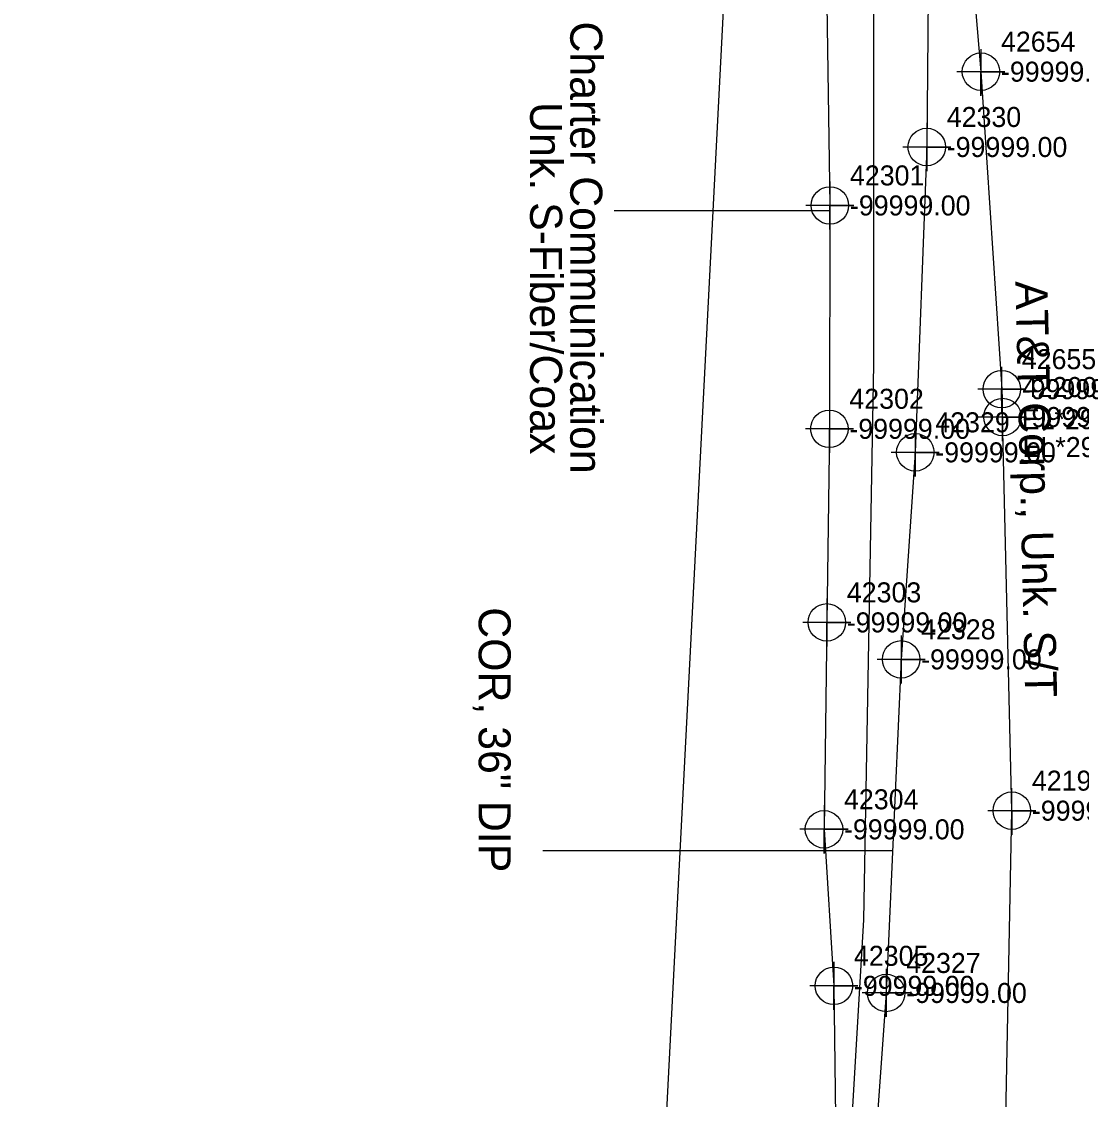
# Model space of a CAD drawing. Extents: x 2083698 to 2094313, y 743246 to 752873.
# Drawn here: x 2093623.5 to 2093755.8, y 746393.7 to 746528.4 of the extents above; entities that cross this region are included whole.
import ezdxf

# ---------------------------------------------------------------- set-up
doc = ezdxf.new("R2010")
doc.units = 0
for name, color, linetype in [('COGO Default Point Number', 7, 'Continuous'), ('Default Symbol CELL', 7, 'Continuous'), ('Default Symbol Cogo Number', 7, 'Continuous'), ('Exist Property Line', 7, 'Continuous'), ('Exist Property Line Leader', 7, 'Continuous'), ('Exist Right of Way Line', 7, 'Continuous'), ('Exist Right of Way Line Leader', 7, 'Continuous'), ('Exist Right of Way Line Text', 7, 'Continuous'), ('Exist Utilities Power UG Cable SUE LOS C', 7, 'Continuous'), ('Exist Utilities Telephone UG Conduit SUE LOS B', 7, 'Continuous'), ('Exist Utilities Telephone UG Conduit SUE LOS B Text', 7, 'Continuous'), ('Exist Utilities Telephone UG Conduit SUE LOS D', 7, 'Continuous'), ('Exist Utilities TV UG Cable SUE LOS B', 7, 'Continuous'), ('Exist Utilities TV UG Cable SUE LOS B Leader', 7, 'Continuous'), ('Exist Utilities TV UG Cable SUE LOS B Text', 7, 'Continuous'), ('Exist Utilities Water UG Line SUE LOS B', 7, 'Continuous'), ('Exist Utilities Water UG Line SUE LOS B Leader', 7, 'Continuous'), ('Exist Utilities Water UG Line SUE LOS B Text', 7, 'Continuous'), ('Scratch_Level_2', 7, 'Continuous'), ('Scratch_Level_3', 7, 'Continuous')]:
    doc.layers.add(name, color=color, linetype=linetype)

msp = doc.modelspace()

# ---------------------------------------------------------------- linework, layer by layer
at = {"layer": 'COGO Default Point Number'}
for points in [[(2093736.52, 746515.69), (2093736.52, 746509.69), (2093736.52, 746512.69), (2093739.52, 746512.69), (2093733.52, 746512.69)], [(2093735.09, 746477.55), (2093735.09, 746471.55), (2093735.09, 746474.55), (2093738.09, 746474.55), (2093732.09, 746474.55)], [(2093733.32, 746451.69), (2093733.32, 746445.69), (2093733.32, 746448.69), (2093736.32, 746448.69), (2093730.32, 746448.69)], [(2093731.46, 746410.02), (2093731.46, 746404.02), (2093731.46, 746407.02), (2093734.46, 746407.02), (2093728.46, 746407.02)]]:
    msp.add_lwpolyline(points, dxfattribs=at)
for centre in [(2093736.52, 746512.69), (2093735.09, 746474.55), (2093733.32, 746448.69), (2093731.46, 746407.02)]:
    msp.add_circle(centre, 2.34, dxfattribs=at)
at = {"layer": 'Exist Property Line Leader'}
for points in [[(2093724.43, 746508.39), (2093724.43, 746502.39), (2093724.43, 746505.39), (2093727.43, 746505.39), (2093721.43, 746505.39)], [(2093724.36, 746480.49), (2093724.36, 746474.49), (2093724.36, 746477.49), (2093727.36, 746477.49), (2093721.36, 746477.49)], [(2093724.04, 746456.31), (2093724.04, 746450.31), (2093724.04, 746453.31), (2093727.04, 746453.31), (2093721.04, 746453.31)], [(2093723.69, 746430.46), (2093723.69, 746424.46), (2093723.69, 746427.46), (2093726.69, 746427.46), (2093720.69, 746427.46)], [(2093724.93, 746410.91), (2093724.93, 746404.91), (2093724.93, 746407.91), (2093727.93, 746407.91), (2093721.93, 746407.91)]]:
    msp.add_lwpolyline(points, dxfattribs=at)
for centre in [(2093724.43, 746505.39), (2093724.36, 746477.49), (2093724.04, 746453.31), (2093723.69, 746427.46), (2093724.93, 746407.91)]:
    msp.add_circle(centre, 2.34, dxfattribs=at)
at = {"layer": 'Exist Right of Way Line Text'}
for points in [[(2093743.26, 746524.92), (2093743.29, 746519.1), (2093743.27, 746522.1), (2093746.29, 746522.1), (2093740.29, 746522.1)], [(2093745.85, 746485.25), (2093745.89, 746479.44), (2093745.87, 746482.44), (2093748.89, 746482.44), (2093742.89, 746482.44)], [(2093745.96, 746481.77), (2093745.99, 746475.96), (2093745.97, 746478.96), (2093748.99, 746478.96), (2093742.99, 746478.96)], [(2093747.11, 746432.6), (2093747.15, 746426.79), (2093747.13, 746429.79), (2093750.15, 746429.79), (2093744.15, 746429.79)]]:
    msp.add_lwpolyline(points, dxfattribs=at)
for centre in [(2093743.29, 746522.1), (2093745.89, 746482.44), (2093745.99, 746478.96), (2093747.15, 746429.79)]:
    msp.add_circle(centre, 2.34, dxfattribs=at)
at = {"layer": 'Exist Utilities Power UG Cable SUE LOS C'}
msp.add_line((2093711.24, 746532.37), (2093680.95, 745945.23), dxfattribs=at)
at = {"layer": 'Exist Utilities Telephone UG Conduit SUE LOS B'}
for points in [[(2093736.63, 746599.86), (2093737.4, 746591.68), (2093739.58, 746565.92), (2093743.29, 746522.1), (2093745.89, 746482.44)], [(2093744.82, 746339.36), (2093746.32, 746387.24), (2093747.15, 746429.79), (2093745.99, 746478.96)]]:
    msp.add_lwpolyline(points, dxfattribs=at)
at = {"layer": 'Exist Utilities Telephone UG Conduit SUE LOS D'}
msp.add_lwpolyline([(2093729.86, 746559.98), (2093729.86, 746485.51), (2093728.61, 746416.16), (2093711.62, 746127.01), (2093702.37, 745955.82), (2093693.11, 745784.64), (2093668.68, 745395.41), (2093654.74, 745161.51), (2093649.12, 745054.6), (2093640.35, 744903.62), (2093631.77, 744751.08), (2093623.85, 744627.43), (2093615.93, 744503.79), (2093603.66, 744373.9), (2093590.72, 744165.44), (2093582.98, 744085.27), (2093575.24, 744005.11), (2093571.65, 743852.76), (2093573.5, 743810.29), (2093555.01, 743734.28)], dxfattribs=at)
at = {"layer": 'Exist Utilities TV UG Cable SUE LOS B'}
msp.add_lwpolyline([(2093633.07, 746593.51), (2093662.38, 746588.07), (2093680.36, 746583.68), (2093688.75, 746580.8), (2093702.36, 746567.68), (2093717.61, 746549.77), (2093724.02, 746533.32), (2093724.43, 746505.39), (2093724.36, 746477.49), (2093724.04, 746453.31), (2093723.69, 746427.46), (2093724.93, 746407.91), (2093725.3, 746378.4), (2093722.23, 746347.81), (2093721.14, 746321.95), (2093719.64, 746295.64), (2093717.76, 746269.05), (2093714.55, 746234.07), (2093712.7, 746215.92), (2093712.08, 746194.48), (2093710.35, 746173.75), (2093709.63, 746157.58)], dxfattribs=at)
at = {"layer": 'Exist Utilities TV UG Cable SUE LOS B Leader'}
msp.add_line((2093724.43, 746504.7), (2093697.49, 746504.7), dxfattribs=at)
at = {"layer": 'Exist Utilities Water UG Line SUE LOS B'}
msp.add_lwpolyline([(2093832.85, 746602.72), (2093832.73, 746608.35), (2093811.86, 746607.74), (2093806.56, 746605.16), (2093803.62, 746603.5), (2093798, 746599.01), (2093792.14, 746592.97), (2093779.17, 746578.82), (2093769.32, 746569.86), (2093759.88, 746559.01), (2093739.27, 746538.9), (2093736.7, 746531.62), (2093736.52, 746512.69), (2093735.09, 746474.55), (2093733.32, 746448.69), (2093731.46, 746407.02), (2093729.37, 746377.81)], dxfattribs=at)
at = {"layer": 'Exist Utilities Water UG Line SUE LOS B Leader'}
msp.add_line((2093732.25, 746424.76), (2093688.56, 746424.76), dxfattribs=at)

# ---------------------------------------------------------------- texts
at = {"layer": 'Default Symbol CELL'}
for s, p in [('42301', (2093726.93, 746507.89)), ('42302', (2093726.86, 746479.99)), ('42303', (2093726.54, 746455.81)), ('42304', (2093726.19, 746429.96)), ('42305', (2093727.43, 746410.41))]:
    msp.add_text(s, height=2.5, dxfattribs=at).set_placement(p)
at = {"layer": 'Default Symbol Cogo Number'}
for p in [(2093726.93, 746504.14), (2093726.86, 746476.24), (2093726.54, 746452.06), (2093726.19, 746426.21), (2093727.43, 746406.66)]:
    msp.add_text('-99999.00', height=2.5, dxfattribs=at).set_placement(p)
at = {"layer": 'Exist Property Line'}
for p in [(2093739.02, 746511.44), (2093737.59, 746473.3), (2093735.82, 746447.44), (2093733.96, 746405.77)]:
    msp.add_text('-99999.00', height=2.5, dxfattribs=at).set_placement(p)
at = {"layer": 'Exist Right of Way Line'}
for s, p in [('42330', (2093739.02, 746515.19)), ('42329', (2093737.59, 746477.05)), ('42328', (2093735.82, 746451.19)), ('42327', (2093733.96, 746409.52))]:
    msp.add_text(s, height=2.5, dxfattribs=at).set_placement(p)
at = {"layer": 'Exist Right of Way Line Leader'}
for s, p in [('42654', (2093745.79, 746524.6)), ('42655', (2093748.39, 746484.94)), ('42200', (2093748.49, 746481.46)), ('42199', (2093749.65, 746432.29))]:
    msp.add_text(s, height=2.5, dxfattribs=at).set_placement(p)
at = {"layer": 'Exist Utilities Telephone UG Conduit SUE LOS B Text'}
msp.add_text('AT&T Corp., Unk. S/T', height=4, rotation=271.3467, dxfattribs=at).set_placement((2093747.59, 746495.92))
at = {"layer": 'Exist Utilities TV UG Cable SUE LOS B Text'}
for s, p in [('Charter Communication', (2093692, 746528.37)), ('Unk. S-Fiber/Coax', (2093686.99, 746518.29))]:
    msp.add_text(s, height=4, rotation=270, dxfattribs=at).set_placement(p)
at = {"layer": 'Exist Utilities Water UG Line SUE LOS B Text'}
msp.add_text('COR, 36" DIP', height=4, rotation=270, dxfattribs=at).set_placement((2093680.56, 746455.2))
at = {"layer": 'Scratch_Level_2'}
for p in [(2093745.79, 746520.85), (2093748.39, 746481.19), (2093748.49, 746477.71), (2093749.65, 746428.54)]:
    msp.add_text('-99999.00', height=2.5, dxfattribs=at).set_placement(p)
at = {"layer": 'Scratch_Level_3'}
for p in [(2093748.39, 746477.44), (2093748.49, 746473.96)]:
    msp.add_text('EL*2972', height=2.5, dxfattribs=at).set_placement(p)

doc.saveas('drawing.dxf')
